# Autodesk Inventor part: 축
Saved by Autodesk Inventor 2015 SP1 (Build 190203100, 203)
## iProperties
Created: 2026-07
Part Number: 축
Material: 일반
Document SubType Name: Modeling
Designer: user
Density: 1 g/cm^3
Appearance: 기본값
Author: user
Author: jhkim
Creation Date: 2026-07-01
Sending System: Autodesk Inventor 2027
Preprocessor: ST-DEVELOPER v20.1
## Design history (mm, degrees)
node "축1"
node "솔리드1"
node "기준1"
